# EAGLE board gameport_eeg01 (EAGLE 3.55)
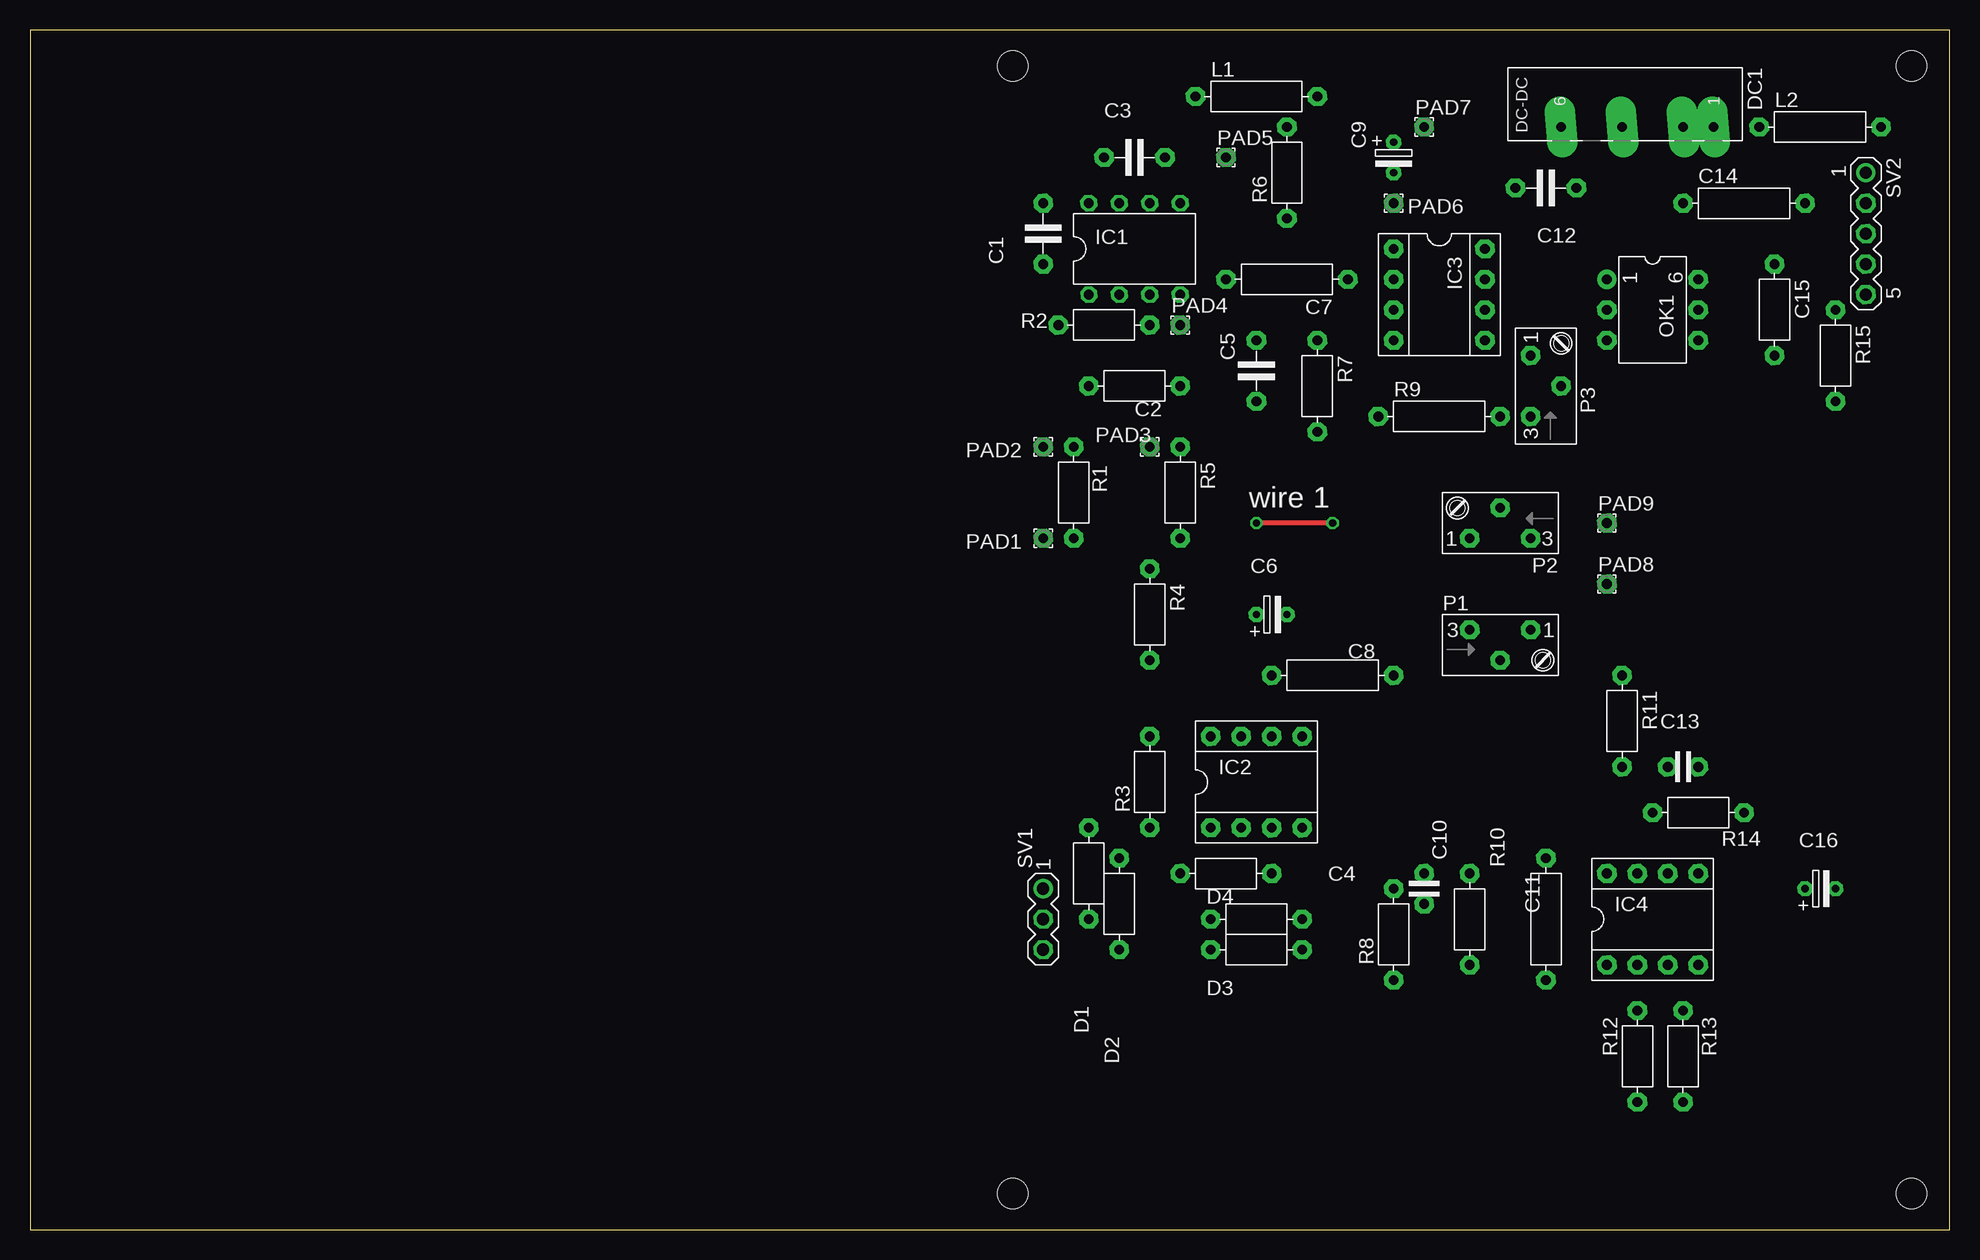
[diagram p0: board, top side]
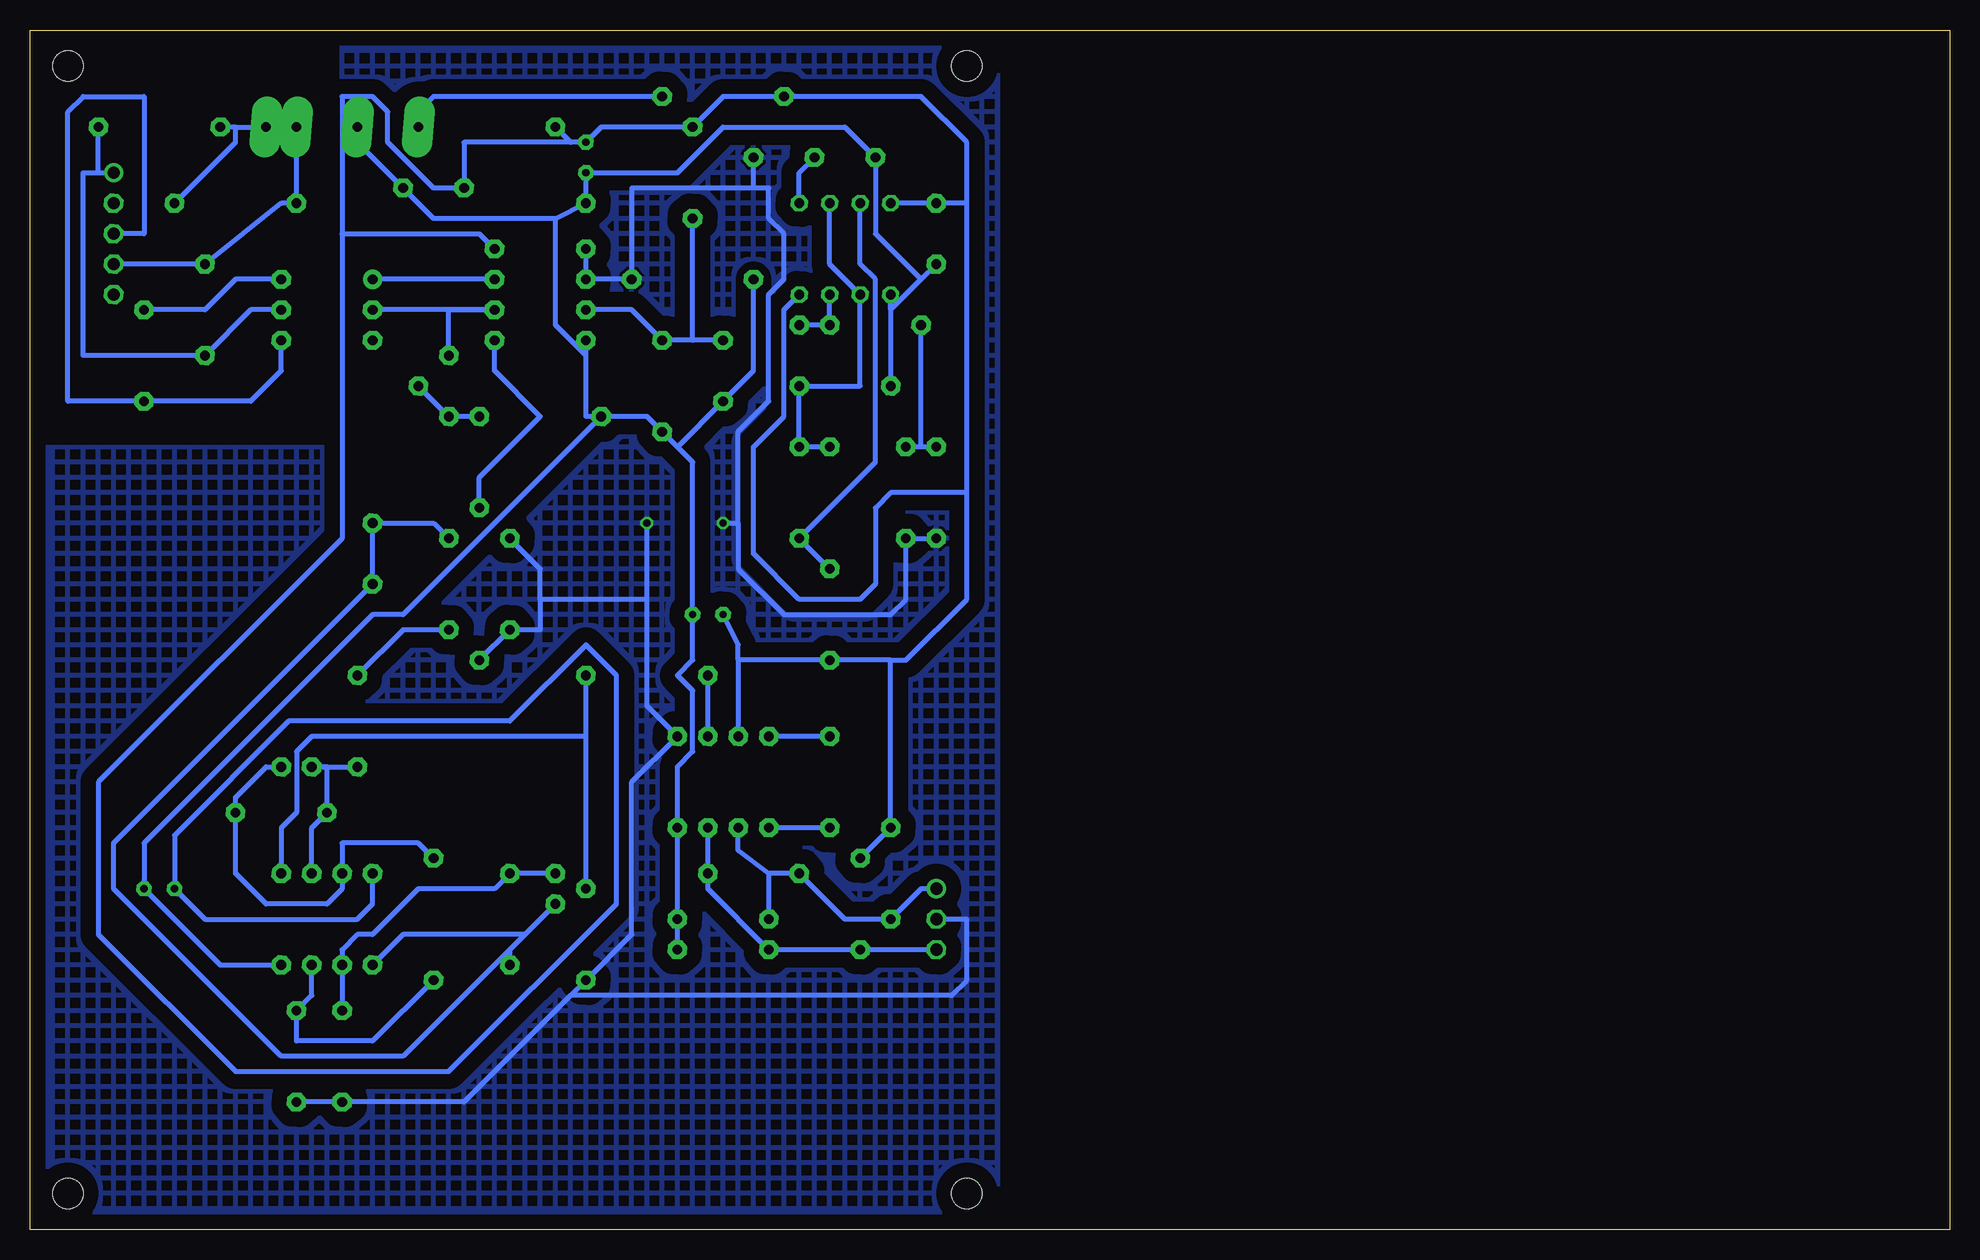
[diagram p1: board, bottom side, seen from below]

Size 160 x 100 mm. Coordinates in mm from the lower left corner, seen from the top.
Outline: 0,0 160,0 160,100 0,100 0,0
Copper layers used: Top, Bottom
Holes 2.54 mm at 156.84,96.99 156.84,3.01 81.91,3.01 81.91,96.99
bRestrict: 3 lines

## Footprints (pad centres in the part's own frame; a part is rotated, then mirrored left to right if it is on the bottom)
5 = drill 0.813 pad 1.6 octagon:  -2.54,0;  2.54,0
7,5 = drill 0.813 pad 1.6 octagon:  -3.81,0;  3.81,0
-2,5 = drill 0.61 pad 1.27 octagon:  -1.27,0;  1.27,0
10 = drill 0.813 pad 1.6 octagon:  -5.08,0;  5.08,0
2,5 = drill 0.813 pad 1.6 octagon:  -1.27,0;  1.27,0
AS = drill 0.813 pad 2.54 long:  1.27,6.35;  1.27,3.81;  1.27,-1.27;  1.27,-6.35
L-08 = drill 0.813 pad 1.397 octagon:  -3.81,-3.81;  -1.27,-3.81;  -1.27,3.81;  -3.81,3.81;  1.27,-3.81;  3.81,-3.81;  1.27,3.81;  3.81,3.81
P-08 = drill 0.813 pad 1.6 octagon:  -3.81,-3.81;  -1.27,-3.81;  3.81,3.81;  1.27,3.81;  1.27,-3.81;  3.81,-3.81;  -1.27,3.81;  -3.81,3.81
L06 = drill 0.813 pad 1.6 round:  -2.54,-3.81 | drill 0.813 pad 1.6 octagon:  0,-3.81;  2.54,-3.81;  2.54,3.81;  0,3.81;  -2.54,3.81
4Y = drill 0.813 pad 1.6 octagon:  2.54,1.27;  -2.54,1.27;  0,-1.27
6/0,8 = drill 0.813 pad 1.6 octagon:  0,0
03-1 = drill 1.016 pad 1.6 round:  -2.54,0 | drill 1.016 pad 1.6 octagon:  0,0;  2.54,0
05-1 = drill 1.016 pad 1.6 round:  -5.08,0 | drill 1.016 pad 1.6 octagon:  -2.54,0;  0,0;  2.54,0;  5.08,0

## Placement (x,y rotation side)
C1  100nF  [5]  84.45,83.02 90 top
C2  47nF  [7,5]  92.07,70.32 0 top
C3  100nF  [5]  92.07,89.37 0 top
C4  22nF  [7,5]  99.69,29.68 180 top
C5  100nF  [5]  102.23,71.59 270 top
C6  47æF  [-2,5]  103.5,51.27 0 top
C7  1æF  [10]  104.77,79.21 180 top
C8  1æF  [10]  108.58,46.19 0 top
C9  47æF  [-2,5]  113.66,89.37 270 top
C10  22nF  [2,5]  116.2,28.41 270 top
C11  1æF  [10]  126.36,25.87 270 top
C12  100nF  [5]  126.36,86.83 180 top
C13  1nF  [2,5]  137.79,38.57 0 top
C14  1æF  [10]  142.87,85.56 0 top
C15  0.3æF  [7,5]  145.41,76.67 270 top
C16  47æF  [-2,5]  149.22,28.41 0 top
D1  BAT48  [7,5]  88.26,29.68 90 top
D2  BAT48  [7,5]  90.8,27.14 90 top
D3  BAT48  [7,5]  102.23,23.33 180 top
D4  BAT48  [7,5]  102.23,25.87 180 top
DC1  TMA0512S  [AS]  133.98,93.18 270 top
IC1  7555CN  [L-08]  92.07,81.75 0 top
IC2  INA114P  [P-08]  102.23,37.3 0 top
IC3  OPA2604AP  [P-08]  117.47,77.94 270 top
IC4  OPA2604AP  [P-08]  135.25,25.87 0 top
L1  20æH  [10]  102.23,94.45 0 top
L2  20æH  [10]  149.22,91.91 0 top
OK1  CNY17-2  [L06]  135.25,76.67 270 top
P1  10k  [4Y]  122.55,48.73 0 top
P2  100k  [4Y]  122.55,58.89 180 top
P3  5k  [4Y]  126.36,70.32 90 top
PAD1  Cal_GND  [6/0,8]  84.45,57.62 0 top
PAD2  U_cal  [6/0,8]  84.45,65.24 0 top
PAD3  cal_off  [6/0,8]  93.34,65.24 0 top
PAD4  full_scale_cal  [6/0,8]  95.88,75.4 0 top
PAD5  AGND  [6/0,8]  99.69,89.37 0 top
PAD6  -Ub  [6/0,8]  113.66,85.56 0 top
PAD7  +Ub  [6/0,8]  116.2,91.91 0 top
PAD8  Uout  [6/0,8]  131.44,53.81 0 top
PAD9  Uin  [6/0,8]  131.44,58.89 0 top
R1  43  [7,5]  86.99,61.43 90 top
R2  10M  [7,5]  89.53,75.4 0 top
R3  5k6  [7,5]  93.34,37.3 90 top
R4  100k  [7,5]  93.34,51.27 270 top
R5  1.5M  [7,5]  95.88,61.43 270 top
R6  100k  [7,5]  104.77,88.1 90 top
R7  100k  [7,5]  107.31,70.32 270 top
R8  1M  [7,5]  113.66,24.6 90 top
R9  470  [10]  117.47,67.78 0 top
R10  200k  [7,5]  120.01,25.87 270 top
R11  1k  [7,5]  132.71,42.38 270 top
R12  1k  [7,5]  133.98,14.44 90 top
R13  1M  [7,5]  137.79,14.44 90 top
R14  200k  [7,5]  139.06,34.76 0 top
R15  100k  [7,5]  150.49,72.86 270 top
SV1  MA03-1  [03-1]  84.45,25.87 270 top
SV2  MA05-1  [05-1]  153.03,83.02 270 top

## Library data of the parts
C1-C16 D1-D4 L1 L2 R1-R15 = DISCRETE
DC1 = DC-DC
IC1 = _work01
IC2-IC4 = BURR
OK1 = OPTOCPL
P1-P3 = TRIMPOT
PAD1-PAD9 = WIREPAD
SV1 SV2 = CON-LSTB

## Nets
+5V: C15. L2. OK1. SV2.
+UB: C1. C6. C9. C12. C16. D1. D2. IC1. IC2. IC3. IC4. L1. PAD7. R4. R6.
-UB: C1. C2. C3. C5. C6. C7. C9. C12. C16. D3. D4. DC1. IC1. IC2. IC3. IC4. PAD6. R7. R9.
AGND: C7. IC2. IC3. P1. P2. PAD1. PAD5. R1. R8. R12. R13. SV1.
DGND: C14. C15. DC1. SV2.
N$1: OK1. R15.
N$2: C4. D2. D3. IC2. SV1.
N$3: IC2. R3.
N$5: C5. IC3. R6. R7.
N$6: IC2. R3.
N$8: IC3. OK1.
N$9: IC3. P2.
N$11: C3. IC1.
N$12: C8. IC2.
N$13: C8. IC4. R8.
N$14: P3. R9.
N$15: C4. D1. D4. IC2. SV1.
N$16: C13. IC4. R11. R14.
N$17: C11. C13. IC4. R14.
N$18: PAD2. R1. R2.
N$19: C11. IC4. R13.
N$20: IC3. OK1. P3.
N$21: IC1. R4. R5.
N$22: C10. IC4. R10. R12.
N$23: C14. DC1. L2.
N$24: OK1. R15. SV2.
N$26: P1. R11.
N$27: C2. IC1. PAD3. R5.
N$29: IC1. PAD4. R2.
N$39: DC1. L1.
UOUT: C10. IC4. P2. PAD8. PAD9. R10.

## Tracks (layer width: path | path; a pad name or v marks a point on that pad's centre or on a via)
+5V
  Bottom 0.406: 154.3,88.1 L2. | 154.3,88.1 155.57,88.1 155.57,72.86 C15. 141.6,76.67 139.06,76.67 | 154.3,88.1 153.03,88.1
+UB
  Bottom 0.406: 100.96,47.46 100.96,41.11 | 100.96,47.46 100.96,48.73 102.23,51.27 | IC4. 131.44,27.14 132.71,25.87 145.41,25.87 147.95,28.41 147.95,32.85 138.42,42.38 120.01,42.38 113.66,48.73 111.12,46.19 111.12,27.14 125.09,13.17 142.87,13.17 154.3,24.6 154.3,37.3 133.98,57.62 133.98,83.02 | 100.96,47.46 R4. 88.26,47.46 | 81.91,85.56 C1. 88.26,85.56 81.91,85.56 | 81.91,85.56 81.91,90.64 85.72,94.45 97.15,94.45 102.23,94.45 R6. 112.39,91.91 113.66,90.64 114.93,90.64 | 88.26,47.46 86.99,47.46 81.91,52.54 81.91,61.43 | IC3. 122.55,83.02 133.98,83.02 | 133.98,83.02 133.98,94.45 131.44,94.45 130.17,93.18 130.17,90.64 126.36,86.83 C12. 123.82,90.64 114.93,90.64 | 95.88,77.94 97.15,76.67 97.15,67.78 99.69,65.24 99.69,56.35 95.88,52.54 90.8,52.54 89.53,53.81 89.53,60.16 88.26,61.43 81.91,61.43 | 81.91,61.43 81.91,85.56 | 114.93,90.64 PAD7. | D2. D1. 88.26,47.46
-UB
  Bottom 0.406: 88.26,76.67 88.26,70.32 | 88.26,76.67 88.26,77.94 | 85.72,79.21 88.26,76.67 | 85.72,79.21 84.45,80.48 | 85.72,79.21 89.53,83.02 89.53,89.37 92.07,91.91 102.23,91.91 106.04,88.1 C9. PAD6. 116.2,84.29 | 132.71,91.91 132.71,90.64 128.9,86.83 126.36,84.29 116.2,84.29 | 139.06,22.06 144.14,22.06 C16. 150.49,32.22 131.44,51.27 128.9,51.27 112.39,67.78 | 106.04,23.33 106.04,25.87 106.04,33.49 106.04,38.57 104.77,39.84 104.77,44.92 106.04,46.19 104.77,47.46 C6. 104.77,63.97 106.04,65.24 | 106.04,65.24 R7. 108.58,67.78 112.39,67.78 | 106.04,65.24 C5. 99.69,71.59 C7. | 113.66,72.86 113.66,74.13 | 112.39,67.78 113.66,67.78 113.66,72.86 | 116.2,84.29 116.2,75.4 113.66,72.86
AGND  (via drill 0.61 pad 1.02)
  Top 0.406: v108.58,58.89 v102.23,58.89
  Bottom 0.406: PAD1. 86.99,57.62 86.99,52.54 88.26,51.27 97.15,51.27 100.96,55.08 100.96,58.89 | 113.66,81.75 113.66,79.21 109.85,79.21 109.85,86.83 99.69,86.83 | 100.96,58.89 100.96,66.51 98.42,69.05 98.42,77.94 97.15,79.21 97.15,83.02 98.42,84.29 98.42,86.83 99.69,86.83 | 114.93,19.52 113.66,20.79 109.85,24.6 109.85,37.3 106.04,41.11 108.58,43.65 108.58,52.54 | 114.93,19.52 123.82,10.63 133.98,10.63 137.79,10.63 | 108.58,52.54 117.47,52.54 | 117.47,52.54 117.47,50 120.01,50 P1. | 117.47,52.54 117.47,55.08 120.01,57.62 | 84.45,25.87 81.91,25.87 81.91,20.79 83.18,19.52 114.93,19.52 | 108.58,52.54 v108.58,58.89 | v102.23,58.89 100.96,58.89 | 99.69,86.83 PAD5.
  pour Bottom (isolate 1.27, hatched): 79.37,99.53 79.37,0.47 160.01,0.47 160.01,65.24 133.98,65.24 133.98,99.53
DGND
  Bottom 0.406: 137.79,91.91 137.79,85.56 139.06,85.56 145.41,80.48 153.03,80.48
N$1
  Bottom 0.406: OK1. 142.87,79.21 145.41,76.67 150.49,76.67
N$2
  Bottom 0.406: SV1. 90.8,23.33 D3. 103.5,28.41 103.5,29.68 103.5,33.49
N$3
  Bottom 0.406: R3. IC2.
N$5
  Bottom 0.406: 104.77,74.13 107.31,74.13 109.85,76.67 113.66,76.67 | 102.23,74.13 104.77,74.13 | 104.77,74.13 104.77,84.29
N$6
  Bottom 0.406: 93.34,33.49 98.42,33.49
N$8
  Bottom 0.406: 121.28,79.21 131.44,79.21
N$9
  Bottom 0.406: P2. 122.55,62.7 117.47,67.78 121.28,71.59 121.28,74.13
N$11
  Bottom 0.406: IC1. 95.88,88.1 C3.
N$12
  Bottom 0.406: 103.5,41.11 103.5,46.19
N$13
  Bottom 0.406: 139.06,29.68 139.06,33.49 137.79,34.76 137.79,39.84 136.52,41.11 113.66,41.11 | 113.66,41.11 C8. | R8. 113.66,41.11
N$14
  Bottom 0.406: P3. 125.09,67.78 R9.
N$15
  Bottom 0.406: 84.45,28.41 85.72,28.41 88.26,25.87 89.53,25.87 92.07,25.87 C4. 98.42,29.68 | 98.42,29.68 D4. | 98.42,29.68 100.96,31.58 100.96,33.49
N$16
  Bottom 0.406: R11. 136.52,38.57 135.25,38.57 135.25,34.76 136.52,33.49 136.52,29.68
N$17
  Bottom 0.406: C13. 140.33,38.57 142.87,36.03 R14. 142.87,29.68 140.33,27.14 135.25,27.14 133.98,28.41 133.98,29.68 133.98,32.22 127.63,32.22 126.36,30.95
N$18
  Bottom 0.406: PAD2. 85.72,65.24 | 85.72,65.24 R1. | 85.72,65.24 85.72,75.4
N$19
  Bottom 0.406: C11. 131.44,15.71 137.79,15.71 R13. 136.52,19.52 136.52,22.06
N$20
  Bottom 0.406: 125.09,72.86 125.09,76.67 121.28,76.67 131.44,76.67
N$21
  Bottom 0.406: 90.8,85.56 90.8,80.48 89.53,79.21 89.53,63.97 R5. 93.34,55.08
N$22
  Bottom 0.406: R12. 133.98,22.06 133.98,23.33 132.71,24.6 131.44,24.6 127.63,28.41 121.28,28.41 120.01,29.68 116.2,29.68
N$23
  Bottom 0.406: 142.87,91.91 140.33,91.91 | 142.87,91.91 144.14,91.91 | 142.87,91.91 142.87,90.64 C14.
N$24
  Bottom 0.406: 153.03,83.02 150.49,83.02 150.49,94.45 155.57,94.45 156.84,93.18 156.84,69.05 R15. 141.6,69.05 139.06,71.59 139.06,74.13
N$26
  Bottom 0.406: 125.09,50 128.9,50 132.71,46.19
N$27
  Bottom 0.406: 93.34,85.56 93.34,80.48 90.8,77.94 90.8,70.32 C2. 95.88,65.24 PAD3.
N$29
  Bottom 0.406: 93.34,77.94 R2. PAD4.
N$39
  Bottom 0.406: L1. 126.36,94.45 127.63,93.18 DC1.
UOUT
  Bottom 0.406: 118.74,24.6 120.01,23.33 | C10. 118.74,24.6 | 120.01,23.33 R10. | 131.44,22.06 128.9,24.6 118.74,24.6 | 120.01,23.33 128.9,14.44 139.06,14.44 153.03,28.41 153.03,32.22 PAD8. PAD9. 126.36,58.89 125.09,57.62

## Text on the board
tPlace: wire 1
